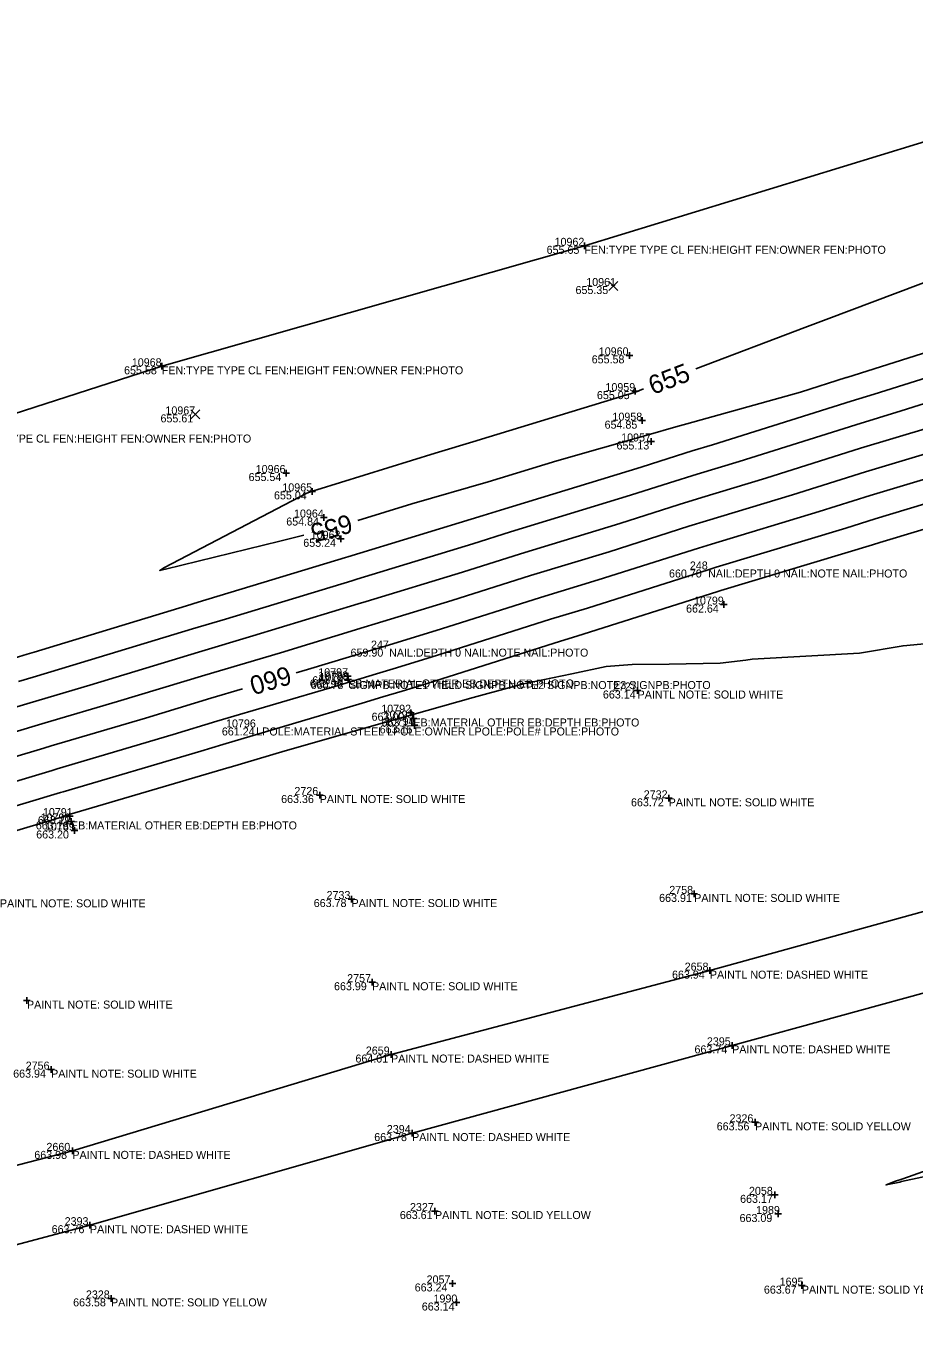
# Model space of a CAD drawing. Extents: x 2129350 to 2137777, y 657588 to 659885.
# Drawn here: x 2131232.5 to 2131365.7, y 658197 to 658391 of the extents above; entities that cross this region are included whole.
import ezdxf

# ---------------------------------------------------------------- set-up
doc = ezdxf.new("R2010")
doc.units = 0
for name, color, linetype in [('DT_X_Contour_Major', 7, 'Continuous'), ('DT_X_Contour_Minor', 7, 'Continuous'), ('DT_X_TIN_Hull', 7, 'Continuous'), ('PV_X_COP', 7, 'Continuous'), ('SV_X_Random_Point', 7, 'Continuous'), ('SV_X_Shot_Marker', 7, 'Continuous'), ('SV_X_Text_Comment', 7, 'Continuous'), ('SV_X_Text_Elevation', 7, 'Continuous'), ('SV_X_Text_Name', 7, 'Continuous')]:
    doc.layers.add(name, color=color, linetype=linetype)

msp = doc.modelspace()

# ---------------------------------------------------------------- linework, layer by layer
at = {"layer": 'DT_X_Contour_Major'}
for points in [[(2131425.74, 658376.75), (2131415.41, 658372.85), (2131402.6, 658367.19), (2131394.42, 658364.05), (2131379.56, 658357.4), (2131378.56, 658357.01), (2131375.94, 658355.84), (2131370.13, 658353.63), (2131352.5, 658346.98), (2131349.32, 658345.77), (2131332.94, 658339.59)], [(2131282.29, 658316.86), (2131290.39, 658319.34), (2131301.79, 658322.63), (2131312.1, 658325.78), (2131325.81, 658329.7), (2131329.94, 658330.86), (2131331.6, 658331.31), (2131348.65, 658336.1), (2131355.51, 658338.27), (2131355.6, 658338.3), (2131378.12, 658345.4)], [(2131325.09, 658336.58), (2131323.91, 658336.08), (2131300.18, 658328.85), (2131300, 658328.8), (2131293.86, 658326.93), (2131276.12, 658321.45), (2131275.44, 658321.24), (2131275.41, 658321.23), (2131274.62, 658320.93), (2131253.3, 658309.81), (2131252.57, 658309.37), (2131253.18, 658309.51), (2131253.42, 658309.57), (2131270.59, 658313.77), (2131274.19, 658314.65)], [(2131368.57, 658323.46), (2131359.1, 658320.61), (2131351.45, 658318.2), (2131335.28, 658313.32), (2131333.36, 658312.71), (2131318.33, 658307.94), (2131309.67, 658305.3), (2131294.83, 658300.6), (2131286.21, 658297.97), (2131284.15, 658297.36), (2131274.74, 658294.5), (2131273.01, 658293.99)], [(2131264.96, 658291.61), (2131260.22, 658290.21), (2131250.41, 658287.23), (2131236.29, 658283.06), (2131236.29, 658283.06), (2131235.18, 658282.72), (2131221.08, 658278.5), (2131211.24, 658275.67), (2131196.67, 658271.31), (2131187.31, 658268.62), (2131185.27, 658268.03), (2131172.47, 658264.15), (2131169.07, 658263.23)]]:
    msp.add_lwpolyline(points, dxfattribs=at)
at = {"layer": 'DT_X_Contour_Minor'}
for points in [[(2131230.11, 658296.02), (2131232.69, 658296.8), (2131232.69, 658296.8), (2131233.74, 658297.11), (2131256.56, 658304.05), (2131258.35, 658304.58), (2131280.44, 658311.3), (2131280.79, 658311.4), (2131301.05, 658317.58), (2131303.66, 658318.41), (2131324.77, 658324.85), (2131327.55, 658325.73), (2131332.42, 658327.27), (2131335.47, 658328.19), (2131356.23, 658334.74), (2131359.68, 658335.78), (2131380.03, 658342.19)], [(2131231.38, 658292.69), (2131233.59, 658293.36), (2131233.59, 658293.36), (2131237.9, 658294.64), (2131257.48, 658300.59), (2131262.45, 658302.06), (2131281.37, 658307.81), (2131282.14, 658308.04), (2131299.49, 658313.33), (2131305.16, 658315.13), (2131323.16, 658320.62), (2131329, 658322.48), (2131333.13, 658323.78), (2131339.47, 658325.69), (2131356.94, 658331.2), (2131363.75, 658333.26), (2131380.76, 658338.62)], [(2131225.11, 658287.11), (2131232.65, 658289.37), (2131234.49, 658289.93), (2131234.49, 658289.93), (2131242.07, 658292.17), (2131258.39, 658297.13), (2131266.55, 658299.54), (2131282.3, 658304.33), (2131283.5, 658304.68), (2131297.94, 658309.09), (2131306.67, 658311.86), (2131321.55, 658316.4), (2131330.45, 658319.22), (2131333.85, 658320.29), (2131343.46, 658323.19), (2131357.66, 658327.67), (2131367.83, 658330.73)], [(2131371.91, 658328.21), (2131358.38, 658324.14), (2131347.45, 658320.69), (2131334.56, 658316.8), (2131331.91, 658315.97), (2131319.94, 658312.17), (2131308.17, 658308.58), (2131296.38, 658304.84), (2131284.85, 658301.33), (2131283.23, 658300.85), (2131270.65, 658297.02), (2131259.31, 658293.67), (2131246.24, 658289.7), (2131235.39, 658286.49), (2131235.39, 658286.49), (2131233.91, 658286.04), (2131223.09, 658282.81)], [(2131380.06, 658323.17), (2131359.82, 658317.08), (2131355.44, 658315.7), (2131335.99, 658309.83), (2131334.81, 658309.46), (2131316.72, 658303.72), (2131311.18, 658302.03), (2131293.27, 658296.35), (2131287.57, 658294.61), (2131285.08, 658293.88), (2131278.84, 658291.98), (2131261.14, 658286.75), (2131254.58, 658284.76), (2131237.2, 658279.62), (2131237.19, 658279.62), (2131236.44, 658279.39), (2131219.06, 658274.19)], [(2131217.04, 658269.89), (2131237.71, 658276.07), (2131238.1, 658276.19), (2131238.1, 658276.19), (2131258.74, 658282.29), (2131262.05, 658283.29), (2131282.94, 658289.46), (2131286.01, 658290.39), (2131288.92, 658291.25), (2131291.72, 658292.11), (2131312.68, 658298.75), (2131315.11, 658299.49), (2131336.26, 658306.2), (2131336.71, 658306.34), (2131359.44, 658313.2), (2131360.54, 658313.55), (2131384.13, 658320.65)], [(2131217.23, 658266.24), (2131238.97, 658272.74), (2131239, 658272.75), (2131239, 658272.75), (2131262.91, 658279.82), (2131262.97, 658279.83), (2131271.38, 658282.32), (2131286.98, 658286.74), (2131289.13, 658287.35), (2131290.36, 658287.71), (2131299.54, 658290.29), (2131305.24, 658291.88), (2131307.12, 658292.37), (2131314.37, 658293.88), (2131319.51, 658294.97), (2131323.42, 658295.25), (2131328.94, 658295.29), (2131336.58, 658295.48), (2131340.45, 658295.92), (2131341.42, 658296.08), (2131357.48, 658296.96), (2131364.03, 658298.06), (2131374.06, 658299.02)], [(2131379.18, 658223.55), (2131364.01, 658218.15), (2131362.76, 658217.74), (2131361.48, 658217.25), (2131363.53, 658217.68), (2131363.78, 658217.74), (2131386.07, 658222.5)]]:
    msp.add_lwpolyline(points, dxfattribs=at)
at = {"layer": 'DT_X_TIN_Hull'}
msp.add_lwpolyline([(2131520.19, 658386.55), (2131475.87, 658361.83), (2131428.42, 658367.86), (2131427.6, 658370.3), (2131426.12, 658375.26), (2131425.33, 658378.33), (2131426.89, 658390.99), (2131371.75, 658375.02), (2131316.24, 658358.02), (2131252.87, 658339.96), (2131221.07, 658329.73), (2131159.94, 658310.93), (2131128.77, 658301.65), (2131077.82, 658286.1), (2131030.27, 658271.69)], dxfattribs=at)
at = {"layer": 'PV_X_COP'}
for points in [[(2131528.03, 658302.66), (2131480.18, 658289.6), (2131431.72, 658276.11), (2131383.73, 658262.83), (2131335.06, 658249.37), (2131287.25, 658236.79), (2131239.47, 658222.35), (2131190.92, 658209.79), (2131142.98, 658196.28), (2131095.12, 658183.57), (2131046.58, 658169.5), (2130997.83, 658156.5), (2130949.67, 658143.39), (2130901.29, 658130.24), (2130853.81, 658116.91), (2130805.18, 658103.5), (2130756.8, 658090.85), (2130709.64, 658077.1)], [(2130712.28, 658065.72), (2130760.53, 658079.19), (2130808.66, 658092.27), (2130856.27, 658105.25), (2130904.86, 658118.78), (2130952.88, 658132.43), (2131001.46, 658145.23), (2131048.98, 658158.95), (2131098.01, 658172.31), (2131145.3, 658185.44), (2131194.12, 658198.4), (2131242.1, 658211.21), (2131290.4, 658225.02), (2131338.4, 658238.17), (2131386.52, 658251.36), (2131434.96, 658264.62), (2131482.99, 658278.86)]]:
    msp.add_lwpolyline(points, dxfattribs=at)
at = {"layer": 'SV_X_Random_Point'}
for p, q in [((2131319.91, 658351.33), (2131321.24, 658352.66)), ((2131319.91, 658352.66), (2131321.24, 658351.33)), ((2131257.24, 658332.08), (2131258.57, 658333.42)), ((2131257.24, 658333.42), (2131258.57, 658332.08))]:
    msp.add_line(p, q, dxfattribs=at)
at = {"layer": 'SV_X_Shot_Marker'}
for p, q in [((2131316.24, 658358.52), (2131316.24, 658357.52)), ((2131315.74, 658358.02), (2131316.74, 658358.02)), ((2131316.24, 658358.02), (2131316.24, 658358.02)), ((2131322.49, 658341.6), (2131323.49, 658341.6)), ((2131322.99, 658342.1), (2131322.99, 658341.1)), ((2131322.99, 658341.6), (2131322.99, 658341.6)), ((2131252.37, 658339.96), (2131253.37, 658339.96)), ((2131252.87, 658340.46), (2131252.87, 658339.46)), ((2131252.87, 658339.96), (2131252.87, 658339.96)), ((2131323.37, 658336.24), (2131324.37, 658336.24)), ((2131323.87, 658336.74), (2131323.87, 658335.74)), ((2131323.87, 658336.24), (2131323.87, 658336.24)), ((2131324.42, 658331.81), (2131325.42, 658331.81)), ((2131324.92, 658332.31), (2131324.92, 658331.31)), ((2131324.92, 658331.81), (2131324.92, 658331.81)), ((2131325.73, 658328.69), (2131326.73, 658328.69)), ((2131326.23, 658329.19), (2131326.23, 658328.19)), ((2131326.23, 658328.69), (2131326.23, 658328.69)), ((2131271.02, 658323.96), (2131272.02, 658323.96)), ((2131271.52, 658324.46), (2131271.52, 658323.46)), ((2131271.52, 658323.96), (2131271.52, 658323.96)), ((2131275.44, 658321.71), (2131275.44, 658320.71)), ((2131274.94, 658321.21), (2131275.94, 658321.21)), ((2131275.44, 658321.21), (2131275.44, 658321.21)), ((2131277.18, 658317.79), (2131277.18, 658316.79)), ((2131276.68, 658317.29), (2131277.68, 658317.29)), ((2131277.18, 658317.29), (2131277.18, 658317.29)), ((2131279.2, 658314.1), (2131280.2, 658314.1)), ((2131279.7, 658314.6), (2131279.7, 658313.6)), ((2131279.7, 658314.1), (2131279.7, 658314.1)), ((2131336.64, 658304.24), (2131337.64, 658304.24)), ((2131337.14, 658304.74), (2131337.14, 658303.74)), ((2131337.14, 658304.24), (2131337.14, 658304.24)), ((2131280.29, 658293.5), (2131281.29, 658293.5)), ((2131280.31, 658293.01), (2131281.31, 658293.01)), ((2131280.79, 658294), (2131280.79, 658293)), ((2131280.79, 658293.5), (2131280.79, 658293.5)), ((2131280.81, 658293.51), (2131280.81, 658292.51)), ((2131280.81, 658293.01), (2131280.81, 658293.01)), ((2131323.72, 658291.36), (2131324.72, 658291.36)), ((2131324.22, 658291.86), (2131324.22, 658290.86)), ((2131324.22, 658291.36), (2131324.22, 658291.36)), ((2131289.73, 658288.03), (2131290.73, 658288.03)), ((2131290.1, 658287.17), (2131291.1, 658287.17)), ((2131290.23, 658288.53), (2131290.23, 658287.53)), ((2131290.23, 658288.03), (2131290.23, 658288.03)), ((2131290.6, 658287.67), (2131290.6, 658286.67)), ((2131290.6, 658287.17), (2131290.6, 658287.17)), ((2131290.25, 658286.14), (2131291.25, 658286.14)), ((2131290.75, 658286.64), (2131290.75, 658285.64)), ((2131290.75, 658286.14), (2131290.75, 658286.14)), ((2131276.05, 658275.69), (2131277.05, 658275.69)), ((2131276.55, 658276.19), (2131276.55, 658275.19)), ((2131276.55, 658275.69), (2131276.55, 658275.69)), ((2131328.38, 658275.2), (2131329.38, 658275.2)), ((2131328.88, 658275.7), (2131328.88, 658274.7)), ((2131328.88, 658275.2), (2131328.88, 658275.2)), ((2131238.56, 658272.53), (2131239.56, 658272.53)), ((2131238.76, 658271.73), (2131239.76, 658271.73)), ((2131239.06, 658273.03), (2131239.06, 658272.03)), ((2131239.06, 658272.53), (2131239.06, 658272.53)), ((2131239.26, 658272.23), (2131239.26, 658271.23)), ((2131239.26, 658271.73), (2131239.26, 658271.73)), ((2131239.3, 658270.38), (2131240.3, 658270.38)), ((2131239.8, 658270.88), (2131239.8, 658269.88)), ((2131239.8, 658270.38), (2131239.8, 658270.38)), ((2131280.83, 658260.1), (2131281.83, 658260.1)), ((2131281.33, 658260.6), (2131281.33, 658259.6)), ((2131281.33, 658260.1), (2131281.33, 658260.1)), ((2131332.21, 658260.87), (2131333.21, 658260.87)), ((2131332.71, 658261.37), (2131332.71, 658260.37)), ((2131332.71, 658260.87), (2131332.71, 658260.87)), ((2131335.06, 658249.87), (2131335.06, 658248.87)), ((2131284.4, 658248.14), (2131284.4, 658247.14)), ((2131334.56, 658249.37), (2131335.56, 658249.37)), ((2131335.06, 658249.37), (2131335.06, 658249.37)), ((2131283.9, 658247.64), (2131284.9, 658247.64)), ((2131284.4, 658247.64), (2131284.4, 658247.64)), ((2131232.16, 658244.88), (2131233.16, 658244.88)), ((2131232.66, 658245.38), (2131232.66, 658244.38)), ((2131232.66, 658244.88), (2131232.66, 658244.88)), ((2131338.4, 658238.67), (2131338.4, 658237.67)), ((2131286.75, 658236.79), (2131287.75, 658236.79)), ((2131287.25, 658237.29), (2131287.25, 658236.29)), ((2131287.25, 658236.79), (2131287.25, 658236.79)), ((2131337.9, 658238.17), (2131338.9, 658238.17)), ((2131338.4, 658238.17), (2131338.4, 658238.17)), ((2131235.78, 658234.53), (2131236.78, 658234.53)), ((2131236.28, 658235.03), (2131236.28, 658234.03)), ((2131236.28, 658234.53), (2131236.28, 658234.53)), ((2131341.33, 658226.63), (2131342.33, 658226.63)), ((2131341.83, 658227.13), (2131341.83, 658226.13)), ((2131341.83, 658226.63), (2131341.83, 658226.63)), ((2131289.9, 658225.02), (2131290.9, 658225.02)), ((2131290.4, 658225.52), (2131290.4, 658224.52)), ((2131290.4, 658225.02), (2131290.4, 658225.02)), ((2131239.47, 658222.85), (2131239.47, 658221.85)), ((2131238.97, 658222.35), (2131239.97, 658222.35)), ((2131239.47, 658222.35), (2131239.47, 658222.35)), ((2131344.29, 658215.76), (2131345.29, 658215.76)), ((2131344.79, 658216.26), (2131344.79, 658215.26)), ((2131344.79, 658215.76), (2131344.79, 658215.76)), ((2131293.34, 658213.33), (2131294.34, 658213.33)), ((2131293.84, 658213.83), (2131293.84, 658212.83)), ((2131293.84, 658213.33), (2131293.84, 658213.33)), ((2131345.31, 658213.39), (2131345.31, 658212.39)), ((2131241.6, 658211.21), (2131242.6, 658211.21)), ((2131242.1, 658211.71), (2131242.1, 658210.71)), ((2131242.1, 658211.21), (2131242.1, 658211.21)), ((2131344.81, 658212.89), (2131345.81, 658212.89)), ((2131345.31, 658212.89), (2131345.31, 658212.89)), ((2131295.95, 658202.48), (2131296.95, 658202.48)), ((2131296.45, 658202.98), (2131296.45, 658201.98)), ((2131296.45, 658202.48), (2131296.45, 658202.48)), ((2131348.35, 658202.15), (2131349.35, 658202.15)), ((2131348.85, 658202.65), (2131348.85, 658201.65)), ((2131348.85, 658202.15), (2131348.85, 658202.15)), ((2131244.76, 658200.23), (2131245.76, 658200.23)), ((2131245.26, 658200.73), (2131245.26, 658199.73)), ((2131245.26, 658200.23), (2131245.26, 658200.23)), ((2131296.56, 658199.62), (2131297.56, 658199.62)), ((2131297.06, 658200.12), (2131297.06, 658199.12)), ((2131297.06, 658199.62), (2131297.06, 658199.62))]:
    msp.add_line(p, q, dxfattribs=at)

# ---------------------------------------------------------------- texts
at = {"layer": 'DT_X_Contour_Major'}
for s, rotation, p in [('655', 20.9445, (2131326.51, 658335.65)), ('655', 195.2788, (2131280.99, 658317.84)), ('660', 196.4529, (2131271.8, 658295.09))]:
    msp.add_text(s, height=2.8, rotation=rotation, dxfattribs=at).set_placement(p)
at = {"layer": 'SV_X_Text_Comment'}
for s, p in [('FEN:TYPE TYPE CL FEN:HEIGHT FEN:OWNER FEN:PHOTO', (2131316.24, 658356.82)), ('FEN:TYPE TYPE CL FEN:HEIGHT FEN:OWNER FEN:PHOTO', (2131252.87, 658338.76)), ('FEN:TYPE TYPE CL FEN:HEIGHT FEN:OWNER FEN:PHOTO', (2131221.08, 658328.53)), ('NAIL:DEPTH 0 NAIL:NOTE NAIL:PHOTO', (2131334.79, 658308.3)), ('NAIL:DEPTH 0 NAIL:NOTE NAIL:PHOTO', (2131286.96, 658296.44)), ('EB:MATERIAL OTHER EB:DEPTH EB:PHOTO', (2131280.81, 658291.81)), ('SIGNPB:NOTE1 YIELD SIGNPB:NOTE2 SIGNPB:NOTE3 SIGNPB:PHOTO', (2131280.96, 658291.58)), ('PAINTL NOTE: SOLID WHITE', (2131324.22, 658290.16)), ('EB:MATERIAL OTHER EB:DEPTH EB:PHOTO', (2131290.6, 658285.97)), ('LPOLE:MATERIAL STEEL LPOLE:OWNER LPOLE:POLE# LPOLE:PHOTO', (2131267.04, 658284.62)), ('PAINTL NOTE: SOLID WHITE', (2131276.55, 658274.49)), ('PAINTL NOTE: SOLID WHITE', (2131328.88, 658274)), ('EB:MATERIAL OTHER EB:DEPTH EB:PHOTO', (2131239.26, 658270.54)), ('PAINTL NOTE: SOLID WHITE', (2131228.6, 658258.86)), ('PAINTL NOTE: SOLID WHITE', (2131281.33, 658258.9)), ('PAINTL NOTE: SOLID WHITE', (2131332.71, 658259.67)), ('PAINTL NOTE: DASHED WHITE', (2131335.06, 658248.17)), ('PAINTL NOTE: SOLID WHITE', (2131284.4, 658246.43)), ('PAINTL NOTE: SOLID WHITE', (2131232.66, 658243.68)), ('PAINTL NOTE: DASHED WHITE', (2131338.4, 658236.97)), ('PAINTL NOTE: DASHED WHITE', (2131287.25, 658235.59)), ('PAINTL NOTE: SOLID WHITE', (2131236.28, 658233.33)), ('PAINTL NOTE: SOLID YELLOW', (2131341.83, 658225.43)), ('PAINTL NOTE: DASHED WHITE', (2131290.4, 658223.82)), ('PAINTL NOTE: DASHED WHITE', (2131239.47, 658221.15)), ('PAINTL NOTE: SOLID YELLOW', (2131293.84, 658212.13)), ('PAINTL NOTE: DASHED WHITE', (2131242.1, 658210.01)), ('PAINTL NOTE: SOLID YELLOW', (2131348.85, 658200.95)), ('PAINTL NOTE: SOLID YELLOW', (2131245.26, 658199.04))]:
    msp.add_text(s, height=1.2, dxfattribs=at).set_placement(p)
at = {"layer": 'SV_X_Text_Elevation'}
for s, p in [('655.65', (2131310.58, 658356.82)), ('655.35', (2131314.91, 658350.79)), ('655.58', (2131317.34, 658340.4)), ('655.58', (2131247.22, 658338.76)), ('655.05', (2131318.12, 658335.04)), ('655.61', (2131252.68, 658331.55)), ('654.85', (2131319.27, 658330.61)), ('655.13', (2131321.06, 658327.49)), ('655.54', (2131265.89, 658322.76)), ('655.04', (2131269.7, 658320.01)), ('654.84', (2131271.54, 658316.09)), ('655.24', (2131274.09, 658312.9)), ('660.70', (2131328.93, 658308.3)), ('662.64', (2131331.49, 658303.04)), ('659.90', (2131281.18, 658296.44)), ('662.96', (2131275.07, 658291.81)), ('660.78', (2131275.19, 658291.58)), ('663.01', (2131275.44, 658292.3)), ('663.14', (2131319.02, 658290.16)), ('663.00', (2131284.33, 658286.83)), ('663.11', (2131285.83, 658285.97)), ('661.24', (2131261.88, 658284.62)), ('663.15', (2131285.55, 658284.93)), ('663.36', (2131270.77, 658274.49)), ('663.72', (2131323.23, 658274)), ('663.16', (2131233.98, 658270.54)), ('663.11', (2131234.29, 658271.32)), ('663.20', (2131234.04, 658269.18)), ('663.78', (2131275.66, 658258.9)), ('663.91', (2131327.45, 658259.67)), ('663.94', (2131329.38, 658248.17)), ('663.99', (2131278.7, 658246.43)), ('663.74', (2131332.75, 658236.97)), ('664.01', (2131281.91, 658235.59)), ('663.94', (2131230.59, 658233.33)), ('663.56', (2131336.08, 658225.43)), ('663.78', (2131284.73, 658223.82)), ('663.98', (2131233.76, 658221.15)), ('663.17', (2131339.59, 658214.56)), ('663.61', (2131288.57, 658212.13)), ('663.76', (2131236.36, 658210.01)), ('663.09', (2131339.51, 658211.69)), ('663.24', (2131290.8, 658201.28)), ('663.67', (2131343.16, 658200.95)), ('663.58', (2131239.58, 658199.04)), ('663.14', (2131291.86, 658198.42))]:
    msp.add_text(s, height=1.2, dxfattribs=at).set_placement(p)
at = {"layer": 'SV_X_Text_Name'}
for s, p in [('10962', (2131311.77, 658358.02)), ('10961', (2131316.52, 658351.99)), ('10968', (2131248.38, 658339.96)), ('10960', (2131318.4, 658341.6)), ('10959', (2131319.4, 658336.24)), ('10967', (2131253.42, 658332.75)), ('10958', (2131320.45, 658331.81)), ('10957', (2131321.76, 658328.69)), ('10966', (2131266.96, 658323.96)), ('10965', (2131270.95, 658321.21)), ('10964', (2131272.7, 658317.29)), ('10963', (2131275.21, 658314.1)), ('248', (2131332.06, 658309.5)), ('10799', (2131332.68, 658304.24)), ('247', (2131284.24, 658297.64)), ('10797', (2131276.34, 658293.5)), ('10798', (2131276.35, 658293.01)), ('10795', (2131276.51, 658292.78)), ('2727', (2131320.51, 658291.36)), ('10792', (2131285.79, 658288.03)), ('10796', (2131262.51, 658285.82)), ('10793', (2131286.15, 658287.17)), ('10794', (2131286.31, 658286.14)), ('2726', (2131272.76, 658275.69)), ('2732', (2131325.14, 658275.2)), ('10791', (2131235.05, 658272.53)), ('10790', (2131234.7, 658271.73)), ('10789', (2131235.36, 658270.38)), ('2758', (2131328.97, 658260.87)), ('2733', (2131277.58, 658260.1)), ('2658', (2131331.28, 658249.37)), ('2757', (2131280.67, 658247.64)), ('2395', (2131334.61, 658238.17)), ('2659', (2131283.47, 658236.79)), ('2756', (2131232.47, 658234.53)), ('2326', (2131338.01, 658226.63)), ('2394', (2131286.62, 658225.02)), ('2660', (2131235.58, 658222.35)), ('2058', (2131340.92, 658215.76)), ('2327', (2131290.09, 658213.33)), ('1989', (2131341.99, 658212.89)), ('2393', (2131238.31, 658211.21)), ('2057', (2131292.58, 658202.48)), ('1695', (2131345.52, 658202.15)), ('2328', (2131241.5, 658200.23)), ('1990', (2131293.62, 658199.62))]:
    msp.add_text(s, height=1.2, dxfattribs=at).set_placement(p)

doc.saveas('drawing.dxf')
